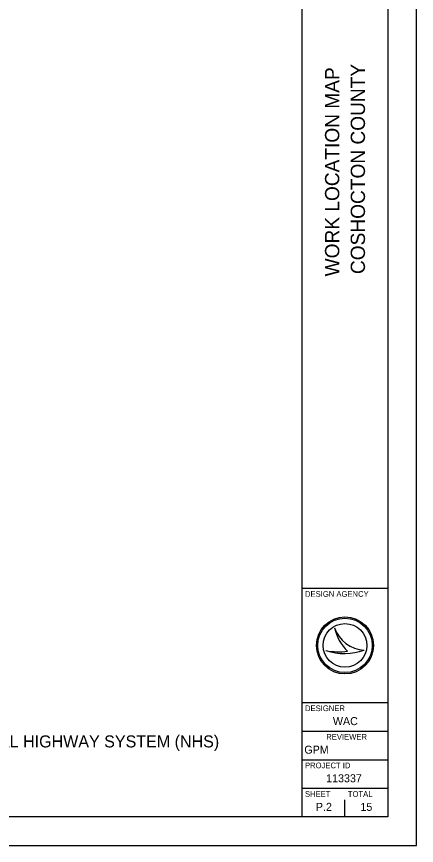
# Model space of a CAD drawing. Extents: x 2004415 to 2276415, y 751181 to 927181.
# Drawn here: x 2220435 to 2276415, y 751181 to 867212 of the extents above; entities that cross this region are included whole.
import ezdxf

# ---------------------------------------------------------------- set-up
doc = ezdxf.new("R2010")
doc.units = 0
for name, color, linetype in [('Default', 7, 'Continuous'), ('SH_Border', 7, 'Continuous'), ('SH_Cut_Line', 7, 'Continuous'), ('SH_Data', 7, 'Continuous')]:
    doc.layers.add(name, color=color, linetype=linetype)

msp = doc.modelspace()

# ---------------------------------------------------------------- linework, layer by layer
at = {"layer": 'SH_Border'}
for p, q in [((2260415, 755181), (2260415, 923181)), ((2260415, 787181), (2272415, 787181)), ((2260415, 771181), (2272415, 771181)), ((2260415, 767181), (2272415, 767181)), ((2260415, 763181), (2272415, 763181)), ((2260415, 759181), (2272415, 759181))]:
    msp.add_line(p, q, dxfattribs=at)
msp.add_lwpolyline([(2016415, 923181), (2272415, 923181), (2272415, 755181), (2016415, 755181)], close=True, dxfattribs=at)
at = {"layer": 'SH_Cut_Line'}
msp.add_lwpolyline([(2004415, 751181), (2276415, 751181), (2276415, 927181), (2004415, 927181)], close=True, dxfattribs=at)
at = {"layer": 'SH_Data'}
for p, q in [((2264955, 781657), (2264955, 781657)), ((2266415, 779181), (2266415, 779181)), ((2263753, 778457), (2263753, 778457)), ((2269114, 778529), (2269114, 778529)), ((2263415, 756581), (2263415, 756581)), ((2266415, 755181), (2266415, 757581))]:
    msp.add_line(p, q, dxfattribs=at)
for radius in [4000, 3814, 3814, 3058]:
    msp.add_circle((2266415, 779181), radius, dxfattribs=at)
for centre, radius, start, end in [((2269343, 783162), 4639, 198.92567, 198.93195), ((2271189, 782941), 6365, 191.63793, 191.64215), ((2269343, 783162), 4639, 198.93195, 267.16574), ((2271189, 782941), 6365, 191.64215, 226.09467), ((2266331, 786141), 8105, 251.45764, 290.08324), ((2265599, 788415), 10128, 259.49639, 259.49952), ((2266331, 786141), 8105, 251.45274, 251.45764), ((2265599, 788415), 10128, 259.49952, 276.66723)]:
    msp.add_arc(centre, radius, start, end, dxfattribs=at)

# ---------------------------------------------------------------- texts
at = {"layer": 'Default'}
msp.add_text('NATIONAL HIGHWAY SYSTEM (NHS)', height=1680, dxfattribs=at).set_placement((2209485, 764901))
at = {"layer": 'SH_Data'}
for s, p in [('WORK LOCATION MAP', (2265615, 830839)), ('COSHOCTON COUNTY', (2269215, 831166))]:
    msp.add_text(s, height=2000, rotation=90, dxfattribs=at).set_placement(p)
for s, height, p in [('DESIGN AGENCY', 800, (2260815, 785981)), ('DESIGNER', 800, (2260815, 769981)), ('WAC', 1120, (2264720, 768021)), ('REVIEWER', 800, (2263790, 765981)), ('GPM', 1120, (2260722, 764021)), ('PROJECT ID', 800, (2260815, 761981)), ('113337', 1120, (2263774, 760021)), ('SHEET', 800, (2260815, 757981)), ('TOTAL', 800, (2266815, 757981)), ('P.2', 1120, (2262339, 756021)), ('15', 1120, (2268573, 756021))]:
    msp.add_text(s, height=height, dxfattribs=at).set_placement(p)

doc.saveas('drawing.dxf')
